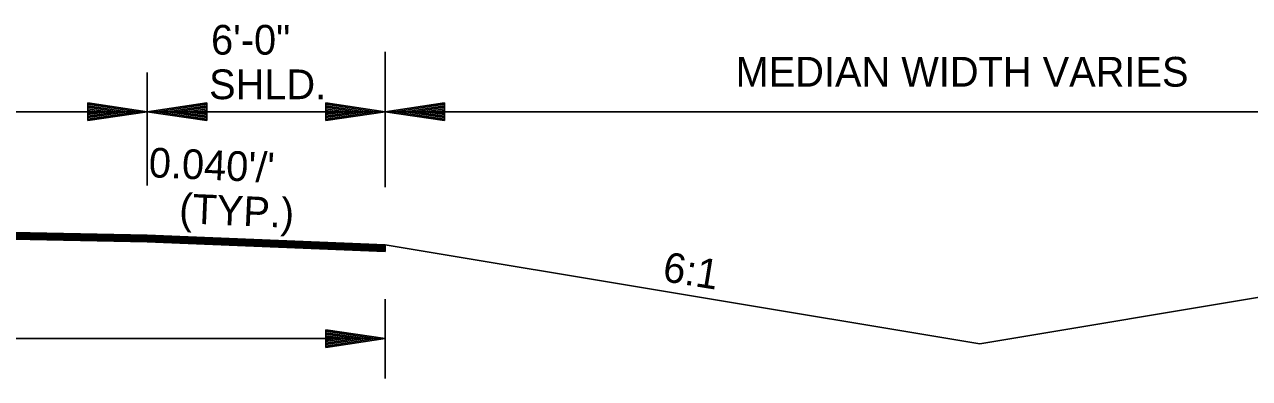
# Model space of a CAD drawing. Extents: x 542112 to 1930787, y -1968972 to 596640.
# Drawn here: x 544703.6 to 545012.5, y -1950497.6 to -1950408.2 of the extents above; entities that cross this region are included whole.
import ezdxf

# ---------------------------------------------------------------- set-up
doc = ezdxf.new("R2010")
doc.units = 0
doc.layers.add('R_Draft', color=7, linetype='Continuous')

msp = doc.modelspace()

# ---------------------------------------------------------------- linework, layer by layer
at = {"layer": 'R_Draft'}
for p, q in [((544794.54, -1950415.15), (544794.54, -1950449.31)), ((544734.54, -1950448.92), (544734.54, -1950420.37)), ((544719.54, -1950428.01), (544734.54, -1950430.26)), ((544719.54, -1950428.01), (544719.54, -1950432.51)), ((544749.54, -1950428.01), (544734.54, -1950430.26)), ((544749.54, -1950428.01), (544749.54, -1950432.51)), ((544779.54, -1950428.01), (544794.54, -1950430.26)), ((544779.54, -1950428.01), (544779.54, -1950432.51)), ((544809.54, -1950428.01), (544794.54, -1950430.26)), ((544809.54, -1950428.01), (544809.54, -1950432.51)), ((544614.54, -1950430.26), (544734.54, -1950430.26)), ((544719.54, -1950428.39), (544732.04, -1950430.26)), ((544719.54, -1950428.77), (544729.46, -1950430.26)), ((544719.54, -1950429.14), (544726.96, -1950430.26)), ((544719.54, -1950429.53), (544724.42, -1950430.26)), ((544719.54, -1950429.91), (544721.91, -1950430.26)), ((544719.54, -1950432.51), (544734.54, -1950430.26)), ((544719.54, -1950431), (544724.42, -1950430.26)), ((544719.54, -1950431.75), (544729.46, -1950430.26)), ((544719.54, -1950432.14), (544732.04, -1950430.26)), ((544719.54, -1950431.38), (544726.96, -1950430.26)), ((544719.54, -1950430.61), (544721.91, -1950430.26)), ((544734.54, -1950430.26), (544794.54, -1950430.26)), ((544749.54, -1950432.51), (544734.54, -1950430.26)), ((544749.54, -1950428.39), (544737.05, -1950430.26)), ((544749.54, -1950432.14), (544737.05, -1950430.26)), ((544749.54, -1950428.77), (544739.63, -1950430.26)), ((544749.54, -1950431.75), (544739.63, -1950430.26)), ((544749.54, -1950429.14), (544742.12, -1950430.26)), ((544749.54, -1950431.38), (544742.12, -1950430.26)), ((544749.54, -1950429.53), (544744.67, -1950430.26)), ((544749.54, -1950431), (544744.67, -1950430.26)), ((544749.54, -1950429.91), (544747.17, -1950430.26)), ((544749.54, -1950430.61), (544747.17, -1950430.26)), ((544779.54, -1950428.39), (544792.04, -1950430.26)), ((544779.54, -1950428.77), (544789.46, -1950430.26)), ((544779.54, -1950429.14), (544786.96, -1950430.26)), ((544779.54, -1950429.53), (544784.42, -1950430.26)), ((544779.54, -1950429.91), (544781.91, -1950430.26)), ((544779.54, -1950432.51), (544794.54, -1950430.26)), ((544779.54, -1950431), (544784.42, -1950430.26)), ((544779.54, -1950431.75), (544789.46, -1950430.26)), ((544779.54, -1950432.14), (544792.04, -1950430.26)), ((544779.54, -1950431.38), (544786.96, -1950430.26)), ((544779.54, -1950430.61), (544781.91, -1950430.26)), ((544809.54, -1950432.51), (544794.54, -1950430.26)), ((545094.54, -1950430.26), (544794.54, -1950430.26)), ((544809.54, -1950428.39), (544797.05, -1950430.26)), ((544809.54, -1950432.14), (544797.05, -1950430.26)), ((544809.54, -1950428.77), (544799.63, -1950430.26)), ((544809.54, -1950431.75), (544799.63, -1950430.26)), ((544809.54, -1950429.14), (544802.12, -1950430.26)), ((544809.54, -1950431.38), (544802.12, -1950430.26)), ((544809.54, -1950429.53), (544804.67, -1950430.26)), ((544809.54, -1950431), (544804.67, -1950430.26)), ((544809.54, -1950429.91), (544807.17, -1950430.26)), ((544809.54, -1950430.61), (544807.17, -1950430.26)), ((544554.54, -1950457.87), (544734.54, -1950461.47)), ((544554.54, -1950458.17), (544734.54, -1950461.77)), ((544554.54, -1950458.47), (544734.54, -1950462.07)), ((544554.54, -1950458.77), (544734.54, -1950462.37)), ((544554.54, -1950459.07), (544734.54, -1950462.67)), ((544554.54, -1950459.37), (544734.54, -1950462.97)), ((544554.54, -1950459.53), (544734.54, -1950463.13)), ((544734.52, -1950462.07), (544794.54, -1950464.47)), ((544734.53, -1950461.77), (544794.54, -1950464.17)), ((544734.54, -1950461.47), (544794.54, -1950463.87)), ((544734.48, -1950463.13), (544794.54, -1950465.53)), ((544734.5, -1950462.97), (544794.54, -1950465.37)), ((544734.51, -1950462.67), (544794.54, -1950465.07)), ((544734.52, -1950462.37), (544794.54, -1950464.77)), ((544794.54, -1950463.87), (544944.54, -1950488.87)), ((544794.54, -1950463.87), (544794.54, -1950465.53)), ((545094.54, -1950463.87), (544944.54, -1950488.87)), ((544794.54, -1950477.63), (544794.54, -1950497.63)), ((544779.54, -1950485.3), (544794.54, -1950487.55)), ((544779.54, -1950485.3), (544779.54, -1950489.8)), ((544779.54, -1950485.68), (544792.04, -1950487.55)), ((544779.54, -1950486.06), (544789.46, -1950487.55)), ((544779.54, -1950486.44), (544786.96, -1950487.55)), ((544779.54, -1950486.83), (544784.42, -1950487.55)), ((544314.54, -1950487.55), (544794.54, -1950487.55)), ((544779.54, -1950487.2), (544781.91, -1950487.55)), ((544779.54, -1950489.8), (544794.54, -1950487.55)), ((544779.54, -1950488.29), (544784.42, -1950487.55)), ((544779.54, -1950489.05), (544789.46, -1950487.55)), ((544779.54, -1950489.43), (544792.04, -1950487.55)), ((544779.54, -1950488.67), (544786.96, -1950487.55)), ((544779.54, -1950487.91), (544781.91, -1950487.55))]:
    msp.add_line(p, q, dxfattribs=at)

# ---------------------------------------------------------------- texts
for s, p in [('6\'-0" ', (544750.63, -1950415.84)), ('MEDIAN WIDTH VARIES', (544882.92, -1950423.92)), ('SHLD.', (544750.13, -1950427.09))]:
    msp.add_text(s, height=7.5, dxfattribs=at).set_placement(p)
for s, rotation, p in [("  0.040'/'", 357.552, (544729.24, -1950446.55)), (' (TYP.)', 357.552, (544739.7, -1950458.26)), ('6:1', 350.8466, (544864.24, -1950472.99))]:
    msp.add_text(s, height=7.5, rotation=rotation, dxfattribs=at).set_placement(p)

doc.saveas('drawing.dxf')
